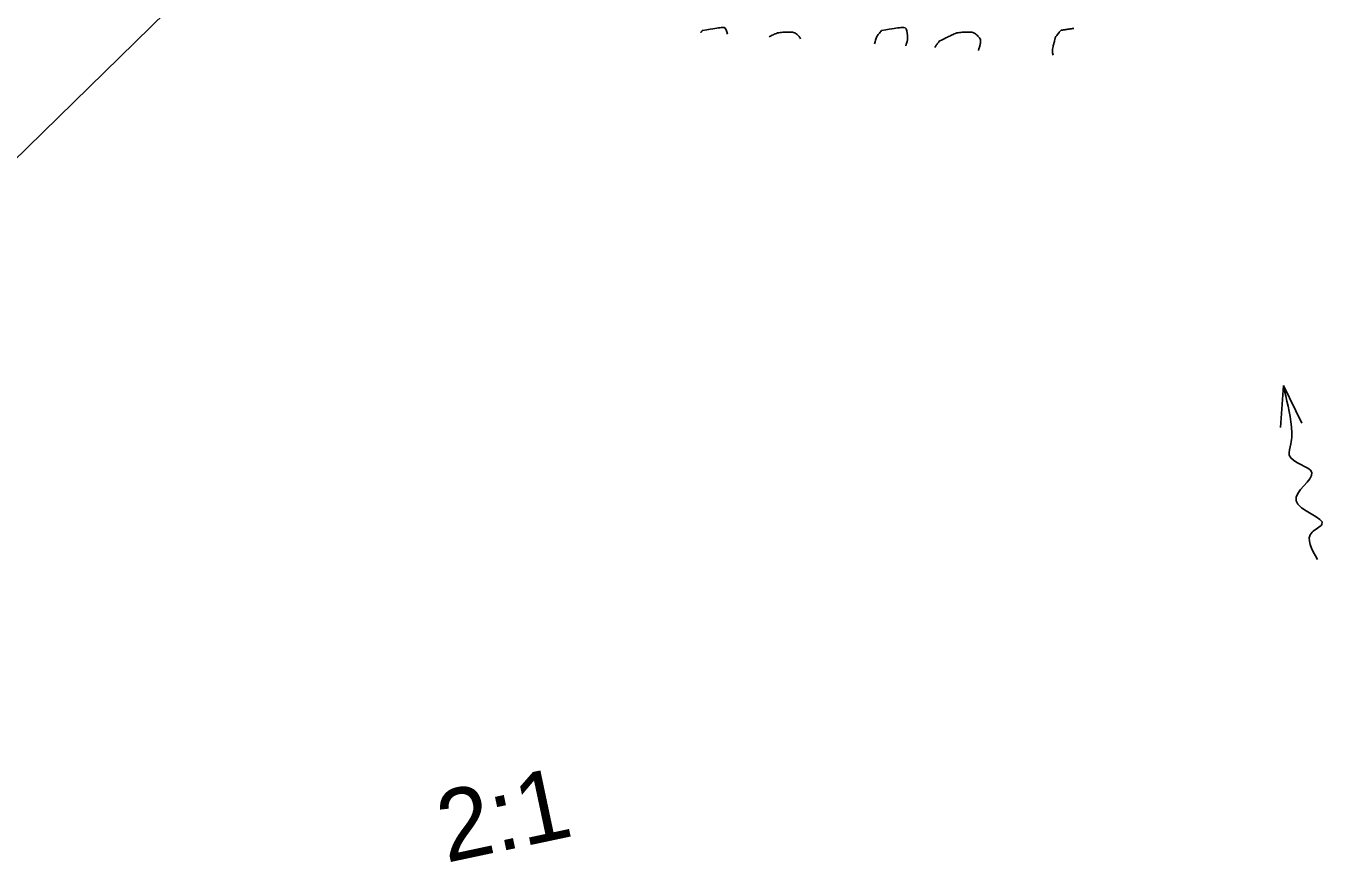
# Model space of a CAD drawing. Extents: x -1577 to 2037, y 0 to 220.
# Drawn here: x 77.06 to 102.72, y 115.9 to 132.4 of the extents above; entities that cross this region are included whole.
import ezdxf

# ---------------------------------------------------------------- set-up
doc = ezdxf.new("R2010")
doc.units = 0
for name, color, linetype in [('GE_P_Alignment_100_Stations', 7, 'Continuous'), ('SC_Scratch1', 7, 'Continuous'), ('XS_P_Pavt_Surface', 7, 'Continuous')]:
    doc.layers.add(name, color=color, linetype=linetype)

msp = doc.modelspace()

# ---------------------------------------------------------------- linework, layer by layer
at = {"layer": 'GE_P_Alignment_100_Stations'}
msp.add_line((97.737, 150.211), (70.83, 123.877), dxfattribs=at)
at = {"layer": 'SC_Scratch1'}
for p, q in [((101.875, 125.302), (101.818, 124.475)), ((102.239, 124.558), (101.875, 125.302))]:
    msp.add_line(p, q, dxfattribs=at)
msp.add_spline([(101.875, 125.302), (102.033, 124.486), (102.023, 124.149), (101.992, 123.93), (102.435, 123.585), (102.124, 123.03), (102.637, 122.56), (102.44, 122.406), (102.551, 121.868)], degree=3, dxfattribs=at)
at = {"layer": 'XS_P_Pavt_Surface'}
for points, degree in [([(90.377, 132.269), (90.388, 132.283), (90.399, 132.297), (90.41, 132.311)], 2), ([(90.41, 132.311), (90.538, 132.33), (90.665, 132.35), (90.792, 132.367), (90.852, 132.375), (90.887, 132.312), (90.902, 132.235)], 3), ([(91.723, 132.182), (91.748, 132.195), (91.773, 132.207), (91.798, 132.22), (91.889, 132.265), (91.999, 132.274), (92.099, 132.277), (92.172, 132.279), (92.243, 132.262), (92.31, 132.196), (92.326, 132.18), (92.338, 132.161), (92.345, 132.142)], 3), ([(93.808, 132.048), (93.823, 132.103), (93.831, 132.165), (93.866, 132.21), (93.893, 132.244), (93.92, 132.278), (93.946, 132.311)], 3), ([(93.946, 132.311), (94.074, 132.33), (94.201, 132.35), (94.328, 132.367), (94.442, 132.382), (94.468, 132.137), (94.432, 132.039), (94.428, 132.029), (94.424, 132.018), (94.42, 132.008)], 3), ([(95.084, 132.095), (95.167, 132.136), (95.25, 132.178), (95.334, 132.22), (95.425, 132.265), (95.535, 132.274), (95.635, 132.277), (95.708, 132.279), (95.779, 132.262), (95.845, 132.196), (95.906, 132.136), (95.897, 132.056), (95.88, 131.993), (95.872, 131.967), (95.865, 131.941), (95.855, 131.916)], 3), ([(97.333, 131.82), (97.306, 131.894), (97.324, 131.975), (97.344, 132.047), (97.359, 132.102), (97.366, 132.165), (97.402, 132.21), (97.429, 132.244), (97.455, 132.278), (97.482, 132.311)], 3), ([(97.482, 132.311), (97.567, 132.324), (97.652, 132.337), (97.737, 132.349)], 2), ([(94.993, 131.971), (94.998, 131.981), (95.003, 131.99), (95.01, 131.998), (95.034, 132.031), (95.059, 132.062), (95.084, 132.095)], 3)]:
    msp.add_open_spline(points, degree=degree, dxfattribs=at)

# ---------------------------------------------------------------- texts
at = {"layer": 'GE_P_Alignment_100_Stations'}
msp.add_text('2:1', height=1.4, rotation=12, dxfattribs=at).set_placement((85.352, 115.881))

doc.saveas('drawing.dxf')
